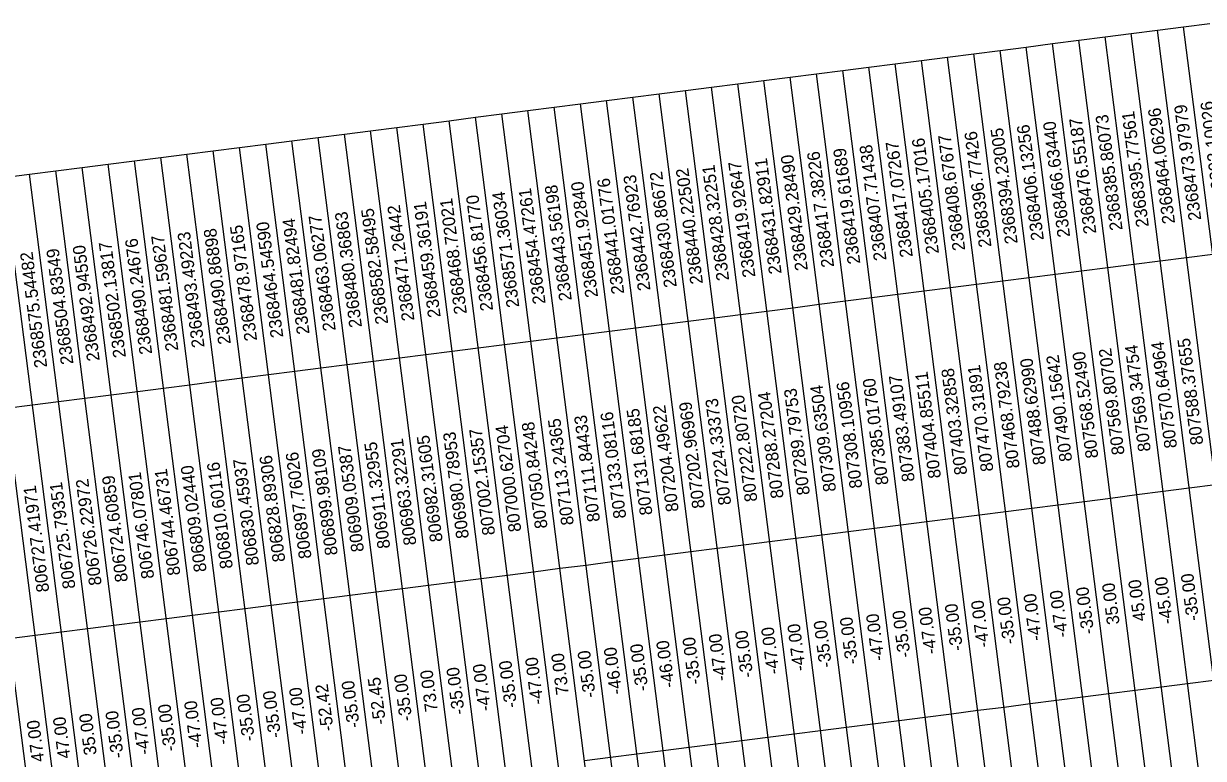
# Model space of a CAD drawing. Extents: x 2364621 to 2374814, y 792603 to 806745.
# Drawn here: x 2369200 to 2371409, y 804137 to 805514 of the extents above; entities that cross this region are included whole.
import ezdxf

# ---------------------------------------------------------------- set-up
doc = ezdxf.new("R2010")
doc.units = 0
doc.layers.add('CTL Sheet Table Cell', color=7, linetype='Continuous')
doc.layers.add('CTL Sheet Text', color=7, linetype='Continuous')

msp = doc.modelspace()

# ---------------------------------------------------------------- linework, layer by layer
at = {"layer": 'CTL Sheet Table Cell'}
for p, q in [((2371274.2, 805495), (2371323.3, 805501.3)), ((2371323.3, 805501.3), (2371372.4, 805507.6)), ((2371557.5, 803667.5), (2371323.3, 805501.3)), ((2371372.4, 805507.6), (2371421.5, 805513.8)), ((2371606.6, 803673.8), (2371372.4, 805507.6)), ((2371126.8, 805476.2), (2371176, 805482.5)), ((2371176, 805482.5), (2371225.1, 805488.7)), ((2371410.2, 803648.7), (2371176, 805482.5)), ((2371225.1, 805488.7), (2371274.2, 805495)), ((2371459.3, 803655), (2371225.1, 805488.7)), ((2371508.4, 803661.3), (2371274.2, 805495)), ((2370930.4, 805451.1), (2370979.5, 805457.4)), ((2370979.5, 805457.4), (2371028.6, 805463.6)), ((2371213.7, 803623.6), (2370979.5, 805457.4)), ((2371028.6, 805463.6), (2371077.7, 805469.9)), ((2371262.8, 803629.9), (2371028.6, 805463.6)), ((2371077.7, 805469.9), (2371126.8, 805476.2)), ((2371311.9, 803636.2), (2371077.7, 805469.9)), ((2371361, 803642.5), (2371126.8, 805476.2)), ((2370783, 805432.3), (2370832.1, 805438.5)), ((2370832.1, 805438.5), (2370881.2, 805444.8)), ((2371066.3, 803604.8), (2370832.1, 805438.5)), ((2370881.2, 805444.8), (2370930.4, 805451.1)), ((2371115.4, 803611.1), (2370881.2, 805444.8)), ((2371164.6, 803617.4), (2370930.4, 805451.1)), ((2370586.5, 805407.2), (2370635.7, 805413.5)), ((2370635.7, 805413.5), (2370684.8, 805419.7)), ((2370869.9, 803579.7), (2370635.7, 805413.5)), ((2370684.8, 805419.7), (2370733.9, 805426)), ((2370919, 803586), (2370684.8, 805419.7)), ((2370733.9, 805426), (2370783, 805432.3)), ((2370968.1, 803592.3), (2370733.9, 805426)), ((2371017.2, 803598.5), (2370783, 805432.3)), ((2370439.2, 805388.4), (2370488.3, 805394.6)), ((2370488.3, 805394.6), (2370537.4, 805400.9)), ((2370722.5, 803560.9), (2370488.3, 805394.6)), ((2370537.4, 805400.9), (2370586.5, 805407.2)), ((2370771.6, 803567.2), (2370537.4, 805400.9)), ((2370820.7, 803573.4), (2370586.5, 805407.2)), ((2370242.7, 805363.3), (2370291.8, 805369.5)), ((2370291.8, 805369.5), (2370340.9, 805375.8)), ((2370526, 803535.8), (2370291.8, 805369.5)), ((2370340.9, 805375.8), (2370390.1, 805382.1)), ((2370575.1, 803542.1), (2370340.9, 805375.8)), ((2370390.1, 805382.1), (2370439.2, 805388.4)), ((2370624.3, 803548.4), (2370390.1, 805382.1)), ((2370673.4, 803554.6), (2370439.2, 805388.4)), ((2370046.2, 805338.2), (2370095.4, 805344.4)), ((2370095.4, 805344.4), (2370144.5, 805350.7)), ((2370329.6, 803510.7), (2370095.4, 805344.4)), ((2370144.5, 805350.7), (2370193.6, 805357)), ((2370378.7, 803517), (2370144.5, 805350.7)), ((2370193.6, 805357), (2370242.7, 805363.3)), ((2370427.8, 803523.3), (2370193.6, 805357)), ((2370476.9, 803529.5), (2370242.7, 805363.3)), ((2369898.9, 805319.4), (2369948, 805325.6)), ((2369948, 805325.6), (2369997.1, 805331.9)), ((2370182.2, 803491.9), (2369948, 805325.6)), ((2369997.1, 805331.9), (2370046.2, 805338.2)), ((2370231.3, 803498.2), (2369997.1, 805331.9)), ((2370280.4, 803504.4), (2370046.2, 805338.2)), ((2369702.4, 805294.3), (2369751.5, 805300.5)), ((2369751.5, 805300.5), (2369800.6, 805306.8)), ((2369985.7, 803466.8), (2369751.5, 805300.5)), ((2369800.6, 805306.8), (2369849.8, 805313.1)), ((2370034.9, 803473.1), (2369800.6, 805306.8)), ((2369849.8, 805313.1), (2369898.9, 805319.4)), ((2370084, 803479.3), (2369849.8, 805313.1)), ((2370133.1, 803485.6), (2369898.9, 805319.4)), ((2369555.1, 805275.4), (2369604.2, 805281.7)), ((2369604.2, 805281.7), (2369653.3, 805288)), ((2369838.4, 803448), (2369604.2, 805281.7)), ((2369653.3, 805288), (2369702.4, 805294.3)), ((2369887.5, 803454.3), (2369653.3, 805288)), ((2369936.6, 803460.5), (2369702.4, 805294.3)), ((2369358.6, 805250.3), (2369407.7, 805256.6)), ((2369407.7, 805256.6), (2369456.8, 805262.9)), ((2369641.9, 803422.9), (2369407.7, 805256.6)), ((2369456.8, 805262.9), (2369505.9, 805269.2)), ((2369691, 803429.2), (2369456.8, 805262.9)), ((2369505.9, 805269.2), (2369555.1, 805275.4)), ((2369740.1, 803435.4), (2369505.9, 805269.2)), ((2369789.3, 803441.7), (2369555.1, 805275.4)), ((2369211.2, 805231.5), (2369260.4, 805237.8)), ((2369260.4, 805237.8), (2369309.5, 805244.1)), ((2369494.6, 803404.1), (2369260.4, 805237.8)), ((2369309.5, 805244.1), (2369358.6, 805250.3)), ((2369543.7, 803410.3), (2369309.5, 805244.1)), ((2369592.8, 803416.6), (2369358.6, 805250.3)), ((2369298.1, 803379), (2369063.9, 805212.7)), ((2369347.2, 803385.2), (2369113, 805219)), ((2369162.1, 805225.3), (2369211.2, 805231.5)), ((2369396.3, 803391.5), (2369162.1, 805225.3)), ((2369445.4, 803397.8), (2369211.2, 805231.5)), ((2371377.7, 805075.6), (2371426.8, 805081.9)), ((2371230.3, 805056.8), (2371279.4, 805063)), ((2371279.4, 805063), (2371328.6, 805069.3)), ((2371328.6, 805069.3), (2371377.7, 805075.6)), ((2371033.8, 805031.7), (2371083, 805038)), ((2371083, 805038), (2371132.1, 805044.2)), ((2371132.1, 805044.2), (2371181.2, 805050.5)), ((2371181.2, 805050.5), (2371230.3, 805056.8)), ((2370837.4, 805006.6), (2370886.5, 805012.9)), ((2370886.5, 805012.9), (2370935.6, 805019.1)), ((2370935.6, 805019.1), (2370984.7, 805025.4)), ((2370984.7, 805025.4), (2371033.8, 805031.7)), ((2370690, 804987.8), (2370739.1, 804994)), ((2370739.1, 804994), (2370788.3, 805000.3)), ((2370788.3, 805000.3), (2370837.4, 805006.6)), ((2370493.6, 804962.7), (2370542.7, 804968.9)), ((2370542.7, 804968.9), (2370591.8, 804975.2)), ((2370591.8, 804975.2), (2370640.9, 804981.5)), ((2370640.9, 804981.5), (2370690, 804987.8)), ((2370346.2, 804943.9), (2370395.3, 804950.1)), ((2370395.3, 804950.1), (2370444.4, 804956.4)), ((2370444.4, 804956.4), (2370493.6, 804962.7)), ((2370149.7, 804918.8), (2370198.8, 804925)), ((2370198.8, 804925), (2370248, 804931.3)), ((2370248, 804931.3), (2370297.1, 804937.6)), ((2370297.1, 804937.6), (2370346.2, 804943.9)), ((2370002.4, 804899.9), (2370051.5, 804906.2)), ((2370051.5, 804906.2), (2370100.6, 804912.5)), ((2370100.6, 804912.5), (2370149.7, 804918.8)), ((2369805.9, 804874.8), (2369855, 804881.1)), ((2369855, 804881.1), (2369904.1, 804887.4)), ((2369904.1, 804887.4), (2369953.3, 804893.7)), ((2369953.3, 804893.7), (2370002.4, 804899.9)), ((2369658.5, 804856), (2369707.7, 804862.3)), ((2369707.7, 804862.3), (2369756.8, 804868.6)), ((2369756.8, 804868.6), (2369805.9, 804874.8)), ((2369462.1, 804830.9), (2369511.2, 804837.2)), ((2369511.2, 804837.2), (2369560.3, 804843.5)), ((2369560.3, 804843.5), (2369609.4, 804849.8)), ((2369609.4, 804849.8), (2369658.5, 804856)), ((2369314.7, 804812.1), (2369363.8, 804818.4)), ((2369363.8, 804818.4), (2369413, 804824.7)), ((2369413, 804824.7), (2369462.1, 804830.9)), ((2369167.4, 804793.3), (2369216.5, 804799.6)), ((2369216.5, 804799.6), (2369265.6, 804805.8)), ((2369265.6, 804805.8), (2369314.7, 804812.1)), ((2371284.7, 804631.1), (2371333.8, 804637.4)), ((2371333.8, 804637.4), (2371382.9, 804643.6)), ((2371382.9, 804643.6), (2371432, 804649.9)), ((2371137.3, 804612.3), (2371186.5, 804618.5)), ((2371186.5, 804618.5), (2371235.6, 804624.8)), ((2371235.6, 804624.8), (2371284.7, 804631.1)), ((2370940.9, 804587.2), (2370990, 804593.4)), ((2370990, 804593.4), (2371039.1, 804599.7)), ((2371039.1, 804599.7), (2371088.2, 804606)), ((2371088.2, 804606), (2371137.3, 804612.3)), ((2370793.5, 804568.4), (2370842.6, 804574.6)), ((2370842.6, 804574.6), (2370891.7, 804580.9)), ((2370891.7, 804580.9), (2370940.9, 804587.2)), ((2370597, 804543.3), (2370646.2, 804549.5)), ((2370646.2, 804549.5), (2370695.3, 804555.8)), ((2370695.3, 804555.8), (2370744.4, 804562.1)), ((2370744.4, 804562.1), (2370793.5, 804568.4)), ((2370449.7, 804524.4), (2370498.8, 804530.7)), ((2370498.8, 804530.7), (2370547.9, 804537)), ((2370547.9, 804537), (2370597, 804543.3)), ((2370253.2, 804499.3), (2370302.3, 804505.6)), ((2370302.3, 804505.6), (2370351.4, 804511.9)), ((2370351.4, 804511.9), (2370400.6, 804518.2)), ((2370400.6, 804518.2), (2370449.7, 804524.4)), ((2370105.9, 804480.5), (2370155, 804486.8)), ((2370155, 804486.8), (2370204.1, 804493.1)), ((2370204.1, 804493.1), (2370253.2, 804499.3)), ((2369909.4, 804455.4), (2369958.5, 804461.7)), ((2369958.5, 804461.7), (2370007.6, 804468)), ((2370007.6, 804468), (2370056.7, 804474.3)), ((2370056.7, 804474.3), (2370105.9, 804480.5)), ((2369762, 804436.6), (2369811.1, 804442.9)), ((2369811.1, 804442.9), (2369860.3, 804449.2)), ((2369860.3, 804449.2), (2369909.4, 804455.4)), ((2369565.6, 804411.5), (2369614.7, 804417.8)), ((2369614.7, 804417.8), (2369663.8, 804424.1)), ((2369663.8, 804424.1), (2369712.9, 804430.3)), ((2369712.9, 804430.3), (2369762, 804436.6)), ((2369418.2, 804392.7), (2369467.3, 804399)), ((2369467.3, 804399), (2369516.4, 804405.2)), ((2369516.4, 804405.2), (2369565.6, 804411.5)), ((2369221.7, 804367.6), (2369270.9, 804373.9)), ((2369270.9, 804373.9), (2369320, 804380.2)), ((2369320, 804380.2), (2369369.1, 804386.4)), ((2369369.1, 804386.4), (2369418.2, 804392.7)), ((2369172.6, 804361.3), (2369221.7, 804367.6)), ((2371232.5, 804258.3), (2371281.6, 804264.6)), ((2371281.6, 804264.6), (2371330.7, 804270.9)), ((2371330.7, 804270.9), (2371379.8, 804277.2)), ((2371379.8, 804277.2), (2371428.9, 804283.4)), ((2371085.1, 804239.5), (2371134.2, 804245.8)), ((2371134.2, 804245.8), (2371183.3, 804252.1)), ((2371183.3, 804252.1), (2371232.5, 804258.3)), ((2370888.6, 804214.4), (2370937.7, 804220.7)), ((2370937.7, 804220.7), (2370986.9, 804227)), ((2370986.9, 804227), (2371036, 804233.2)), ((2371036, 804233.2), (2371085.1, 804239.5)), ((2370692.2, 804189.3), (2370741.3, 804195.6)), ((2370741.3, 804195.6), (2370790.4, 804201.9)), ((2370790.4, 804201.9), (2370839.5, 804208.2)), ((2370839.5, 804208.2), (2370888.6, 804214.4)), ((2370544.8, 804170.5), (2370593.9, 804176.8)), ((2370593.9, 804176.8), (2370643, 804183.1)), ((2370643, 804183.1), (2370692.2, 804189.3)), ((2370348.3, 804145.4), (2370397.5, 804151.7)), ((2370397.5, 804151.7), (2370446.6, 804158)), ((2370446.6, 804158), (2370495.7, 804164.2)), ((2370495.7, 804164.2), (2370544.8, 804170.5)), ((2370250.1, 804132.9), (2370299.2, 804139.1)), ((2370299.2, 804139.1), (2370348.3, 804145.4))]:
    msp.add_line(p, q, dxfattribs=at)

# ---------------------------------------------------------------- texts
at = {"layer": 'CTL Sheet Text'}
for s, height, p in [('2368393.10026', 23.579, (2371454.6, 805152.4)), ('2368395.77561', 23.579, (2371307.3, 805133.6)), ('2368464.06296', 23.579, (2371356.4, 805139.8)), ('2368473.97979', 23.579, (2371405.5, 805146.1)), ('2368406.13256', 23.579, (2371110.8, 805108.5)), ('2368466.63440', 23.579, (2371159.9, 805114.7)), ('2368476.55187', 23.579, (2371209, 805121)), ('2368385.86073', 23.579, (2371258.2, 805127.3)), ('2368408.67677', 23.579, (2370963.5, 805089.6)), ('2368396.77426', 23.579, (2371012.6, 805095.9)), ('2368394.23005', 23.579, (2371061.7, 805102.2)), ('2368419.61689', 23.579, (2370767, 805064.5)), ('2368407.71438', 23.579, (2370816.1, 805070.8)), ('2368417.07267', 23.579, (2370865.2, 805077.1)), ('2368405.17016', 23.579, (2370914.3, 805083.4)), ('2368431.82911', 23.579, (2370619.6, 805045.7)), ('2368429.28490', 23.579, (2370668.7, 805052)), ('2368417.38226', 23.579, (2370717.9, 805058.3)), ('2368430.86672', 23.579, (2370423.2, 805020.6)), ('2368440.22502', 23.579, (2370472.3, 805026.9)), ('2368428.32251', 23.579, (2370521.4, 805033.2)), ('2368419.92647', 23.579, (2370570.5, 805039.5)), ('2368451.92840', 23.579, (2370275.8, 805001.8)), ('2368441.01776', 23.579, (2370324.9, 805008.1)), ('2368442.76923', 23.579, (2370374, 805014.4)), ('2368456.81770', 23.579, (2370079.3, 804976.7)), ('2368571.36034', 23.579, (2370128.4, 804983)), ('2368454.47261', 23.579, (2370177.6, 804989.3)), ('2368443.56198', 23.579, (2370226.7, 804995.5)), ('2368471.26442', 23.579, (2369932, 804957.9)), ('2368459.36191', 23.579, (2369981.1, 804964.2)), ('2368468.72021', 23.579, (2370030.2, 804970.4)), ('2368481.82494', 23.579, (2369735.5, 804932.8)), ('2368463.06277', 23.579, (2369784.6, 804939.1)), ('2368480.36863', 23.579, (2369833.7, 804945.4)), ('2368582.58495', 23.579, (2369882.9, 804951.6)), ('2368493.49223', 23.579, (2369539, 804907.7)), ('2368490.86898', 23.579, (2369588.1, 804914)), ('2368478.97165', 23.579, (2369637.3, 804920.3)), ('2368464.54590', 23.579, (2369686.4, 804926.5)), ('2368502.13817', 23.579, (2369391.7, 804888.9)), ('2368490.24676', 23.579, (2369440.8, 804895.2)), ('2368481.59627', 23.579, (2369489.9, 804901.4)), ('2368575.54482', 23.579, (2369244.3, 804870.1)), ('2368504.83549', 23.579, (2369293.4, 804876.3)), ('2368492.94550', 23.579, (2369342.6, 804882.6)), ('807569.80702', 23.579, (2371261.9, 804706.9)), ('807569.34754', 23.579, (2371311, 804713.2)), ('807570.64964', 23.579, (2371360.2, 804719.5)), ('807588.37655', 23.579, (2371409.3, 804725.7)), ('807488.62990', 23.579, (2371114.6, 804688.1)), ('807490.15642', 23.579, (2371163.7, 804694.4)), ('807568.52490', 23.579, (2371212.8, 804700.6)), ('807404.85511', 23.579, (2370918.1, 804663)), ('807403.32858', 23.579, (2370967.2, 804669.3)), ('807470.31891', 23.579, (2371016.3, 804675.6)), ('807468.79238', 23.579, (2371065.5, 804681.8)), ('807309.63504', 23.579, (2370721.6, 804637.9)), ('807308.10956', 23.579, (2370770.7, 804644.2)), ('807385.01760', 23.579, (2370819.9, 804650.5)), ('807383.49107', 23.579, (2370869, 804656.7)), ('807222.80720', 23.579, (2370574.3, 804619.1)), ('807288.27204', 23.579, (2370623.4, 804625.4)), ('807289.79753', 23.579, (2370672.5, 804631.6)), ('807131.68185', 23.579, (2370377.8, 804594)), ('807204.49622', 23.579, (2370426.9, 804600.3)), ('807202.96969', 23.579, (2370476, 804606.5)), ('807224.33373', 23.579, (2370525.2, 804612.8)), ('807113.24365', 23.579, (2370230.5, 804575.2)), ('807111.84433', 23.579, (2370279.6, 804581.5)), ('807133.08116', 23.579, (2370328.7, 804587.7)), ('806980.78953', 23.579, (2370034, 804550.1)), ('807002.15357', 23.579, (2370083.1, 804556.4)), ('807000.62704', 23.579, (2370132.2, 804562.6)), ('807050.84248', 23.579, (2370181.3, 804568.9)), ('806911.32955', 23.579, (2369886.6, 804531.3)), ('806963.32291', 23.579, (2369935.7, 804537.5)), ('806982.31605', 23.579, (2369984.9, 804543.8)), ('806828.89306', 23.579, (2369690.2, 804506.2)), ('806897.76026', 23.579, (2369739.3, 804512.4)), ('806899.98109', 23.579, (2369788.4, 804518.7)), ('806909.05387', 23.579, (2369837.5, 804525)), ('806809.02440', 23.579, (2369542.8, 804487.4)), ('806810.60116', 23.579, (2369591.9, 804493.6)), ('806830.45937', 23.579, (2369641, 804499.9)), ('806726.22972', 23.579, (2369346.3, 804462.3)), ('806724.60859', 23.579, (2369395.4, 804468.5)), ('806746.07801', 23.579, (2369444.6, 804474.8)), ('806744.46731', 23.579, (2369493.7, 804481.1)), ('806727.41971', 23.579, (2369248.1, 804449.7)), ('806725.79351', 23.579, (2369297.2, 804456)), ('-35.00', 23.58, (2371401.5, 804396.1)), ('35.00', 23.58, (2371252.6, 804388.9)), ('45.00', 23.58, (2371301.7, 804395.2)), ('-45.00', 23.58, (2371352.3, 804389.9)), ('-35.00', 23.58, (2371057.6, 804352.2)), ('-47.00', 23.58, (2371106.8, 804358.5)), ('-47.00', 23.58, (2371155.9, 804364.8)), ('-35.00', 23.58, (2371205, 804371)), ('-47.00', 23.58, (2370910.3, 804333.4)), ('-35.00', 23.58, (2370959.4, 804339.7)), ('-47.00', 23.58, (2371008.5, 804346)), ('-35.00', 23.58, (2370713.8, 804308.3)), ('-35.00', 23.58, (2370762.9, 804314.6)), ('-47.00', 23.58, (2370812, 804320.9)), ('-35.00', 23.58, (2370861.2, 804327.1)), ('-35.00', 23.58, (2370566.5, 804289.5)), ('-47.00', 23.58, (2370615.6, 804295.8)), ('-47.00', 23.58, (2370664.7, 804302)), ('-35.00', 23.58, (2370370, 804264.4)), ('-46.00', 23.58, (2370419.1, 804270.7)), ('-35.00', 23.58, (2370468.2, 804276.9)), ('-47.00', 23.58, (2370517.3, 804283.2)), ('73.00', 23.58, (2370221.1, 804257.2)), ('-35.00', 23.58, (2370271.7, 804251.9)), ('-46.00', 23.58, (2370320.9, 804258.1)), ('-35.00', 23.58, (2370026.2, 804220.5)), ('-47.00', 23.58, (2370075.3, 804226.8)), ('-35.00', 23.58, (2370124.4, 804233)), ('-47.00', 23.58, (2370173.5, 804239.3)), ('-52.45', 23.58, (2369878.8, 804201.7)), ('-35.00', 23.58, (2369927.9, 804207.9)), ('73.00', 23.58, (2369975.6, 804225.8)), ('-35.00', 23.58, (2369682.3, 804176.6)), ('-47.00', 23.58, (2369731.4, 804182.8)), ('-52.42', 23.58, (2369780.6, 804189.1)), ('-35.00', 23.58, (2369829.7, 804195.4)), ('-47.00', 23.58, (2369535, 804157.8)), ('-47.00', 23.58, (2369584.1, 804164)), ('-35.00', 23.58, (2369633.2, 804170.3)), ('35.00', 23.58, (2369337, 804144.3)), ('-35.00', 23.58, (2369387.6, 804138.9)), ('-47.00', 23.58, (2369436.7, 804145.2)), ('-35.00', 23.58, (2369485.9, 804151.5)), ('47.00', 23.58, (2369238.8, 804131.7)), ('47.00', 23.58, (2369287.9, 804138))]:
    msp.add_text(s, height=height, rotation=97.2784, dxfattribs=at).set_placement(p)

doc.saveas('drawing.dxf')
